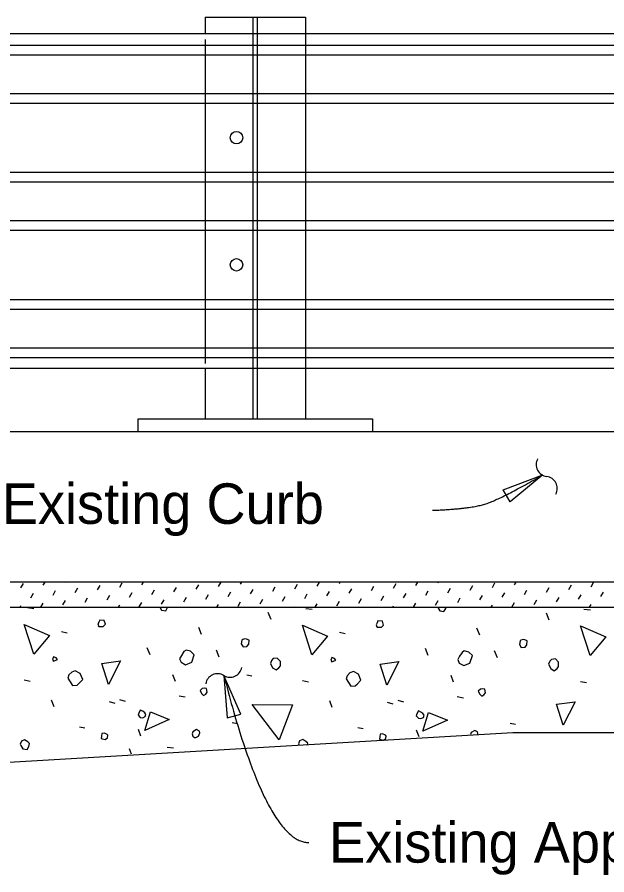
# Model space of a CAD drawing. Extents: x 21587 to 21659.1, y 56116.2 to 56157.3.
# Drawn here: x 21616.36 to 21619.295, y 56132.593 to 56136.864 of the extents above; entities that cross this region are included whole.
import ezdxf

# ---------------------------------------------------------------- set-up
doc = ezdxf.new("R2010")
doc.units = 0
for name, color, linetype in [('AdhocPoint_dp', 7, 'Continuous'), ('Border', 7, 'Continuous'), ('Patterning', 7, 'Continuous'), ('PlotBorder_dp', 7, 'Continuous'), ('SheetBorder_dp', 7, 'Continuous'), ('TextMisc', 7, 'Continuous')]:
    doc.layers.add(name, color=color, linetype=linetype)

msp = doc.modelspace()

# ---------------------------------------------------------------- linework, layer by layer
at = {"layer": 'AdhocPoint_dp'}
for p, q in [((21613.608, 56134.8009), (21621.5551, 56134.8009)), ((21624.3563, 56134.0511), (21613.608, 56134.0511)), ((21613.608, 56133.926), (21624.3563, 56133.926)), ((21618.8279, 56133.301), (21614.6079, 56133.0509)), ((21624.3563, 56133.301), (21618.8279, 56133.301))]:
    msp.add_line(p, q, dxfattribs=at)
at = {"layer": 'Border'}
for p, q in [((21617.2955, 56136.8635), (21617.7955, 56136.8635)), ((21617.2955, 56136.8635), (21617.2955, 56136.7802)), ((21617.7955, 56136.8635), (21617.7955, 56136.7802)), ((21619.5663, 56136.7801), (21607.3117, 56136.7801)), ((21607.3117, 56136.7246), (21619.5663, 56136.7246)), ((21607.3117, 56136.6764), (21619.5663, 56136.6764)), ((21607.3117, 56136.4835), (21619.5663, 56136.4835)), ((21607.3117, 56136.4353), (21619.5663, 56136.4353)), ((21607.3117, 56136.0914), (21619.5663, 56136.0914)), ((21607.3117, 56136.0431), (21619.5663, 56136.0431)), ((21607.3117, 56135.8503), (21619.5663, 56135.8503)), ((21607.3117, 56135.8022), (21619.5663, 56135.8022)), ((21607.3117, 56135.4582), (21619.5663, 56135.4582)), ((21607.3117, 56135.41), (21619.5663, 56135.41)), ((21607.3117, 56135.2172), (21619.5663, 56135.2172)), ((21607.3117, 56135.169), (21619.5663, 56135.169)), ((21619.5663, 56135.1134), (21607.3117, 56135.1134)), ((21617.2955, 56135.1135), (21617.2955, 56134.8635)), ((21617.7955, 56135.1134), (21617.7955, 56134.8635)), ((21616.9622, 56134.8635), (21618.1289, 56134.8635)), ((21616.9622, 56134.801), (21616.9622, 56134.8635)), ((21617.2955, 56134.8635), (21617.7955, 56134.8635)), ((21618.1289, 56134.8635), (21618.1289, 56134.801)), ((21616.9622, 56134.801), (21618.1289, 56134.801))]:
    msp.add_line(p, q, dxfattribs=at)
for centre in [(21617.4518, 56136.2634), (21617.4518, 56135.6303)]:
    msp.add_circle(centre, 0.0312, dxfattribs=at)
at = {"layer": 'Patterning'}
for p, q in [((21617.5351, 56134.8635), (21617.5351, 56136.8635)), ((21617.556, 56134.8635), (21617.556, 56136.8635)), ((21617.7955, 56136.7801), (21617.7955, 56135.1134)), ((21617.2955, 56136.7516), (21617.2955, 56135.1398))]:
    msp.add_line(p, q, dxfattribs=at)
at = {"layer": 'PlotBorder_dp'}
for points in [[(21618.9767, 56134.5845), (21618.814, 56134.4497), (21618.7787, 56134.5108)], [(21617.3888, 56133.5857), (21617.4059, 56133.3752), (21617.4742, 56133.3926)]]:
    msp.add_lwpolyline(points, close=True, dxfattribs=at)
for centre, start, end in [((21619.0033, 56134.636), 151.5267, 263.2539), ((21618.9893, 56134.5176), 331.5267, 83.2539), ((21617.4197, 56133.6363), 238.4384, 350.1656), ((21617.3573, 56133.5347), 58.4384, 170.1656)]:
    msp.add_arc(centre, 0.0596, start, end, dxfattribs=at)
for points in [[(21618.4283, 56134.4081), (21618.6029, 56134.415), (21618.759, 56134.4587), (21618.9767, 56134.5845)], [(21617.3892, 56133.5857), (21617.6004, 56132.7545), (21617.8116, 56132.7545)]]:
    msp.add_open_spline(points, degree=2, dxfattribs=at)
at = {"layer": 'TextMisc'}
for p, q in [((21616.3793, 56134.0219), (21616.3922, 56134.0443)), ((21616.4899, 56134.0349), (21616.4993, 56134.0511)), ((21616.6005, 56134.0479), (21616.6024, 56134.0511)), ((21616.76, 56134.012), (21616.773, 56134.0344)), ((21616.8706, 56134.0249), (21616.8836, 56134.0473)), ((21616.9813, 56134.0379), (21616.9889, 56134.0511)), ((21617.0919, 56134.0509), (21617.092, 56134.0511)), ((21617.2514, 56134.015), (21617.2643, 56134.0374)), ((21617.362, 56134.028), (21617.375, 56134.0504)), ((21617.4726, 56134.0409), (21617.4785, 56134.0511)), ((21617.7427, 56134.018), (21617.7557, 56134.0404)), ((21617.8534, 56134.031), (21617.865, 56134.0511)), ((21617.964, 56134.044), (21617.9681, 56134.0511)), ((21618.2341, 56134.021), (21618.2471, 56134.0434)), ((21618.3447, 56134.034), (21618.3546, 56134.0511)), ((21618.4554, 56134.047), (21618.4578, 56134.0511)), ((21618.6148, 56134.0111), (21618.6278, 56134.0335)), ((21618.7255, 56134.0241), (21618.7384, 56134.0465)), ((21618.8361, 56134.037), (21618.8442, 56134.0511)), ((21618.9467, 56134.05), (21618.9474, 56134.0511)), ((21619.1062, 56134.0141), (21619.1192, 56134.0365)), ((21619.2168, 56134.0271), (21619.2298, 56134.0495)), ((21616.4281, 56133.9731), (21616.4411, 56133.9955)), ((21616.5387, 56133.9861), (21616.5517, 56134.0084)), ((21616.6494, 56133.999), (21616.6623, 56134.0214)), ((21616.9195, 56133.9761), (21616.9324, 56133.9985)), ((21617.0301, 56133.9891), (21617.0431, 56134.0115)), ((21617.1407, 56134.002), (21617.1537, 56134.0244)), ((21617.4108, 56133.9791), (21617.4238, 56134.0015)), ((21617.5215, 56133.9921), (21617.5344, 56134.0145)), ((21617.6321, 56134.0051), (21617.6451, 56134.0275)), ((21617.7916, 56133.9692), (21617.8045, 56133.9916)), ((21617.9022, 56133.9822), (21617.9152, 56134.0045)), ((21618.0128, 56133.9951), (21618.0258, 56134.0175)), ((21618.1235, 56134.0081), (21618.1364, 56134.0305)), ((21618.2829, 56133.9722), (21618.2959, 56133.9946)), ((21618.3936, 56133.9852), (21618.4065, 56134.0076)), ((21618.5042, 56133.9981), (21618.5172, 56134.0205)), ((21618.7743, 56133.9752), (21618.7873, 56133.9976)), ((21618.8849, 56133.9882), (21618.8979, 56134.0106)), ((21618.9956, 56134.0012), (21619.0085, 56134.0235)), ((21619.2657, 56133.9782), (21619.2786, 56134.0006)), ((21616.5876, 56133.9372), (21616.6005, 56133.9596)), ((21616.6982, 56133.9502), (21616.7112, 56133.9726)), ((21616.8088, 56133.9631), (21616.8218, 56133.9855)), ((21616.9683, 56133.9273), (21616.9813, 56133.9497)), ((21617.0789, 56133.9402), (21617.0919, 56133.9626)), ((21617.1896, 56133.9532), (21617.2025, 56133.9756)), ((21617.3002, 56133.9662), (21617.3132, 56133.9886)), ((21617.4597, 56133.9303), (21617.4726, 56133.9527)), ((21617.5703, 56133.9433), (21617.5833, 56133.9657)), ((21617.6809, 56133.9562), (21617.6939, 56133.9786)), ((21617.951, 56133.9333), (21617.964, 56133.9557)), ((21618.0617, 56133.9463), (21618.0746, 56133.9687)), ((21618.1723, 56133.9592), (21618.1853, 56133.9816)), ((21618.4424, 56133.9363), (21618.4554, 56133.9587)), ((21618.553, 56133.9493), (21618.566, 56133.9717)), ((21618.6637, 56133.9623), (21618.6766, 56133.9847)), ((21618.8231, 56133.9264), (21618.8361, 56133.9488)), ((21618.9338, 56133.9394), (21618.9467, 56133.9617)), ((21619.0444, 56133.9523), (21619.0574, 56133.9747)), ((21619.155, 56133.9653), (21619.168, 56133.9877)), ((21616.3748, 56133.926), (21616.3793, 56133.9337)), ((21616.4123, 56133.9236), (21616.4441, 56133.9201)), ((21616.478, 56133.926), (21616.4899, 56133.9466)), ((21616.8645, 56133.926), (21616.8706, 56133.9367)), ((21617.2509, 56133.926), (21617.2514, 56133.9268)), ((21617.3541, 56133.926), (21617.362, 56133.9397)), ((21617.7406, 56133.926), (21617.7427, 56133.9298)), ((21617.7969, 56133.9201), (21617.8288, 56133.9165)), ((21617.8437, 56133.926), (21617.8534, 56133.9427)), ((21618.2302, 56133.926), (21618.2341, 56133.9328)), ((21618.3333, 56133.926), (21618.3447, 56133.9458)), ((21618.7198, 56133.926), (21618.7255, 56133.9358)), ((21619.1816, 56133.9165), (21619.2134, 56133.913)), ((21619.2094, 56133.926), (21619.2168, 56133.9388)), ((21617.6243, 56133.8641), (21617.6102, 56133.8995)), ((21619.009, 56133.8606), (21618.9949, 56133.8959)), ((21617.2785, 56133.7892), (21617.2643, 56133.8246)), ((21618.6631, 56133.7857), (21618.649, 56133.8211)), ((21616.5802, 56133.8051), (21616.6085, 56133.7981)), ((21617.9649, 56133.8016), (21617.9932, 56133.7945)), ((21617.0221, 56133.6885), (21617.008, 56133.7238)), ((21617.3662, 56133.6767), (21617.3521, 56133.7121)), ((21618.4068, 56133.6849), (21618.3927, 56133.7203)), ((21618.7509, 56133.6732), (21618.7368, 56133.7085)), ((21616.3952, 56133.5636), (21616.4253, 56133.5583)), ((21617.1477, 56133.5559), (21617.1353, 56133.5895)), ((21617.5041, 56133.5883), (21617.5289, 56133.5848)), ((21618.5323, 56133.5524), (21618.52, 56133.5859)), ((21617.7799, 56133.5601), (21617.8099, 56133.5547)), ((21619.1646, 56133.5565), (21619.1946, 56133.5512)), ((21617.1665, 56133.484), (21617.1965, 56133.4787)), ((21618.5512, 56133.4805), (21618.5812, 56133.4752)), ((21616.5437, 56133.4292), (21616.5313, 56133.4628)), ((21616.8177, 56133.4558), (21616.846, 56133.4487)), ((21616.8701, 56133.4657), (21616.8984, 56133.4587)), ((21617.9284, 56133.4257), (21617.916, 56133.4593)), ((21618.2024, 56133.4522), (21618.2307, 56133.4451)), ((21618.2548, 56133.4622), (21618.2831, 56133.4551)), ((21617.4299, 56133.3515), (21617.4564, 56133.3462)), ((21616.671, 56133.3302), (21616.6975, 56133.3249)), ((21616.9762, 56133.2831), (21616.9638, 56133.3167)), ((21618.0557, 56133.3267), (21618.0822, 56133.3214)), ((21618.3609, 56133.2796), (21618.3485, 56133.3132)), ((21618.8145, 56133.3479), (21618.8411, 56133.3426)), ((21617.1064, 56133.2295), (21617.1382, 56133.2259)), ((21616.9302, 56133.1935), (21616.9196, 56133.2201))]:
    msp.add_line(p, q, dxfattribs=at)
for points in [[(21617.0705, 56133.926), (21617.0787, 56133.9112), (21617.0999, 56133.9077), (21617.1088, 56133.9236), (21617.1094, 56133.926)], [(21618.4533, 56133.926), (21618.4545, 56133.9236)], [(21618.4545, 56133.9236), (21618.4634, 56133.9077), (21618.4846, 56133.9041), (21618.4934, 56133.9201), (21618.4949, 56133.926)], [(21616.7676, 56133.8299), (21616.7888, 56133.8299), (21616.7994, 56133.8405), (21616.7941, 56133.8599), (21616.7711, 56133.8617), (21616.7676, 56133.8511), (21616.7623, 56133.8423), (21616.7676, 56133.8299), (21616.764, 56133.8334)], [(21616.4429, 56133.6926), (21616.3952, 56133.8394), (21616.5207, 56133.7846), (21616.4429, 56133.6926)], [(21617.8276, 56133.6891), (21617.7799, 56133.8358), (21617.9054, 56133.781), (21617.8276, 56133.6891)], [(21618.1523, 56133.8264), (21618.1735, 56133.8264), (21618.1841, 56133.837), (21618.1788, 56133.8564), (21618.1558, 56133.8582), (21618.1523, 56133.8476), (21618.147, 56133.8387), (21618.1523, 56133.8264), (21618.1487, 56133.8299)], [(21619.2123, 56133.6856), (21619.1646, 56133.8323), (21619.2901, 56133.7775), (21619.2123, 56133.6856)], [(21617.4758, 56133.7439), (21617.4847, 56133.728), (21617.5041, 56133.7298), (21617.513, 56133.7421), (21617.5147, 56133.7616), (21617.5023, 56133.7669), (21617.4935, 56133.7686), (21617.4829, 56133.7651), (21617.4794, 56133.7616), (21617.4758, 56133.7439)], [(21618.8605, 56133.7404), (21618.8693, 56133.7245), (21618.8888, 56133.7262), (21618.8976, 56133.7386), (21618.8994, 56133.758), (21618.887, 56133.7633), (21618.8782, 56133.7651), (21618.8676, 56133.7616), (21618.864, 56133.758), (21618.8605, 56133.7404)], [(21617.1759, 56133.6514), (21617.1989, 56133.639), (21617.229, 56133.6514), (21617.2413, 56133.6885), (21617.2237, 56133.7062), (21617.2007, 56133.7115), (21617.1901, 56133.7044), (21617.1777, 56133.6849), (21617.1689, 56133.669), (21617.1759, 56133.6514)], [(21618.5606, 56133.6478), (21618.5836, 56133.6354), (21618.6136, 56133.6478), (21618.626, 56133.6849), (21618.6083, 56133.7026), (21618.5854, 56133.7079), (21618.5748, 56133.7008), (21618.5624, 56133.6814), (21618.5535, 56133.6655), (21618.5606, 56133.6478)], [(21616.5419, 56133.6573), (21616.5614, 56133.6661), (21616.5543, 56133.6732), (21616.5419, 56133.6785), (21616.5366, 56133.6661), (21616.5419, 56133.6573)], [(21616.8153, 56133.5417), (21616.7817, 56133.646), (21616.8754, 56133.6584), (21616.8153, 56133.5417)], [(21617.6208, 56133.6449), (21617.6314, 56133.6237), (21617.6491, 56133.6131), (21617.6632, 56133.6237), (21617.6703, 56133.6343), (21617.6703, 56133.6555), (21617.6544, 56133.6714), (21617.6349, 56133.6697), (21617.6261, 56133.6608), (21617.6208, 56133.6449)], [(21617.9266, 56133.6537), (21617.9461, 56133.6626), (21617.939, 56133.6697), (21617.9266, 56133.675), (21617.9213, 56133.6626), (21617.9266, 56133.6537)], [(21618.2, 56133.5382), (21618.1664, 56133.6425), (21618.2601, 56133.6549), (21618.2, 56133.5382)], [(21619.0055, 56133.6414), (21619.0161, 56133.6202), (21619.0338, 56133.6096), (21619.0479, 56133.6202), (21619.055, 56133.6308), (21619.055, 56133.652), (21619.0391, 56133.6679), (21619.0196, 56133.6661), (21619.0108, 56133.6573), (21619.0055, 56133.6414)], [(21616.6126, 56133.5724), (21616.6356, 56133.5353), (21616.6586, 56133.5371), (21616.6674, 56133.5459), (21616.6869, 56133.5654), (21616.6745, 56133.5954), (21616.6498, 56133.6096), (21616.6321, 56133.6025), (21616.6179, 56133.5883), (21616.6126, 56133.5724)], [(21617.9973, 56133.5689), (21618.0203, 56133.5318), (21618.0433, 56133.5335), (21618.0521, 56133.5424), (21618.0716, 56133.5618), (21618.0592, 56133.5919), (21618.0344, 56133.606), (21618.0168, 56133.5989), (21618.0026, 56133.5848), (21617.9973, 56133.5689)], [(21617.2778, 56133.4964), (21617.2884, 56133.4858), (21617.2991, 56133.4929), (21617.3061, 56133.5035), (21617.3026, 56133.5212), (21617.2938, 56133.5229), (21617.2814, 56133.5212), (21617.2708, 56133.5106), (21617.2778, 56133.4964)], [(21618.6625, 56133.4929), (21618.6731, 56133.4823), (21618.6837, 56133.4893), (21618.6908, 56133.4999), (21618.6873, 56133.5176), (21618.6784, 56133.5194), (21618.6661, 56133.5176), (21618.6554, 56133.507), (21618.6625, 56133.4929)], [(21617.665, 56133.2648), (21617.5306, 56133.4416), (21617.7304, 56133.4398), (21617.665, 56133.2648)], [(21619.0778, 56133.3385), (21619.0443, 56133.4428), (21619.1379, 56133.4551), (21619.0778, 56133.3385)], [(21616.9726, 56133.3773), (21616.985, 56133.3756), (21616.9974, 56133.3809), (21617.0009, 56133.3915), (21616.9956, 56133.4003), (21616.985, 56133.4074), (21616.9726, 56133.4127), (21616.9656, 56133.3986), (21616.962, 56133.388), (21616.9726, 56133.3773)], [(21616.995, 56133.3126), (21617.0233, 56133.4045), (21617.117, 56133.3674), (21616.995, 56133.3126)], [(21618.3573, 56133.3738), (21618.3697, 56133.372), (21618.3821, 56133.3773), (21618.3856, 56133.388), (21618.3803, 56133.3968), (21618.3697, 56133.4039), (21618.3573, 56133.4092), (21618.3503, 56133.395), (21618.3467, 56133.3844), (21618.3573, 56133.3738)], [(21618.3797, 56133.309), (21618.408, 56133.401), (21618.5017, 56133.3638), (21618.3797, 56133.309)], [(21617.2425, 56133.2772), (21617.2496, 56133.2772), (21617.2637, 56133.2843), (21617.269, 56133.3002), (21617.2672, 56133.309), (21617.2531, 56133.3161), (21617.2354, 56133.3055), (21617.2319, 56133.2949), (21617.2354, 56133.2843), (21617.2425, 56133.2772)], [(21618.6514, 56133.2899), (21618.6537, 56133.2967), (21618.6519, 56133.3055), (21618.6378, 56133.3126), (21618.6201, 56133.302), (21618.6166, 56133.2914), (21618.6177, 56133.2878)], [(21616.3793, 56133.2366), (21616.3881, 56133.2206), (21616.4094, 56133.2171), (21616.4182, 56133.233), (21616.4217, 56133.2472), (21616.4129, 56133.256), (21616.397, 56133.2648), (21616.3811, 56133.2595), (21616.3758, 56133.2436), (21616.3793, 56133.2366)], [(21616.7788, 56133.2719), (21616.7983, 56133.2666), (21616.8106, 56133.2754), (21616.8124, 56133.2878), (21616.8089, 56133.2914), (21616.7947, 56133.2984), (21616.7824, 56133.2967), (21616.7806, 56133.2843), (21616.7788, 56133.2719)], [(21617.8048, 56133.2422), (21617.8064, 56133.2488), (21617.7976, 56133.2577), (21617.7817, 56133.2665), (21617.7657, 56133.2612), (21617.7604, 56133.2453), (21617.7633, 56133.2396)], [(21618.1635, 56133.2684), (21618.1829, 56133.2631), (21618.1953, 56133.2719), (21618.1971, 56133.2843), (21618.1935, 56133.2878), (21618.1794, 56133.2949), (21618.167, 56133.2931), (21618.1653, 56133.2807), (21618.1635, 56133.2684)]]:
    msp.add_lwpolyline(points, dxfattribs=at)

# ---------------------------------------------------------------- texts
at = {"layer": 'SheetBorder_dp'}
for s, p in [('Existing Curb', (21616.2837, 56134.3406)), ('Existing Approach Slab', (21617.9127, 56132.654))]:
    msp.add_text(s, height=0.2016, dxfattribs=at).set_placement(p)

doc.saveas('drawing.dxf')
